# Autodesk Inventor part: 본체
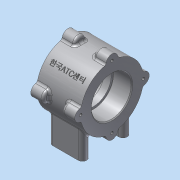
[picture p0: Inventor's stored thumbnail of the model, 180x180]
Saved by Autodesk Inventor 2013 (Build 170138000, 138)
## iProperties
Created: 2015-03
Part Number: 본체
Material: 알루미늄 6061
Document SubType Name: Modeling
Designer: 교육생
Density: 2.71 g/cm^3
Mass: 450.776 g
Surface Area: 332.744 cm^2
Volume: 166.338 cm^3
Author: 교육생
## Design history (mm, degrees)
sketch "스케치1"
  geometry: L1 (19, -31.749)-(19, -56); L2 (19, -56)-(29, -56); L3 (29, -56)-(29, -22.978); L4 (-29, -22.978)-(-29, -56); L5 (-29, -56)-(-19, -56); L6 (-19, -56)-(-19, -31.749); A1 r 37 centre (0, 0) between (19, -31.749) and (29, -22.978); 3 further points
  constraints: 12 end point, 4 parallel, 4 point on circle, 3 horizontal alignment, 2 midpoint, 2 perpendicular, 1 centre point, 1 coincident, 1 vertical
  dimensions: "d0" = 74 diameter of A1; "d4" = 10 distance of L1.end L2.end; "d5" = 56 distance from line of L2 point (0, 0); "d6" = 48 distance of point (24, -56) point (-24, -56)
extrude "돌출1" new body sketch "스케치1" stored distance "d2" = 52; taper "d3" = 0 deg
extrude "돌출2" join sketch "스케치1" stored distance "d7" = 40; taper "d8" = 0 deg
sketch "스케치2"
  geometry: A1 r 37 centre (0, 0) between (0, 37) and (-6.969, 36.338) reference; A2 r 7 centre (0, 37) between (6.969, 36.338) and (-6.969, 36.338)
  constraints: 5 point on circle, 1 centre point, 1 vertical alignment
  dimensions: "d9" = 7 radius of A2
extrude "돌출3" join sketch "스케치2" distance "d11" = 15; taper "d12" = 0 deg
hole "구멍1" diameter "d15" = 3.242; stored, may be unused: countersink angle "d19" = 90 deg, drill point angle "d21" = 118 deg; dims "d13" = 10, "d14" = 10, "d16" = 8, "d17" = 4, "d18" = 2, "d20" = 11
fillet "모깎기1" dims "d25" = 5
fillet "모깎기2" dims "d26" = 3
fillet "모깎기3" dims "d27" = 3
fillet "모깎기4" dims "d28" = 3
fillet "모깎기5" dims "d29" = 3
fillet "모깎기6" dims "d30" = 3
hole "구멍3" diameter "d42" = 4.134; stored, may be unused: countersink angle "d46" = 90 deg, drill point angle "d48" = 118 deg; dims "d40" = 10, "d41" = 10, "d43" = 6, "d44" = 4, "d45" = 2, "d47" = 8
hole "구멍4" diameter "d51" = 4.134; stored, may be unused: countersink angle "d55" = 90 deg, drill point angle "d57" = 118 deg; dims "d49" = 10, "d50" = 10, "d52" = 6, "d53" = 4, "d54" = 2, "d56" = 8
hole "구멍5" diameter "d60" = 4.134; stored, may be unused: countersink angle "d64" = 90 deg, drill point angle "d66" = 118 deg; dims "d58" = 10, "d59" = 10, "d61" = 6, "d62" = 4, "d63" = 2, "d65" = 8
hole "구멍6" diameter "d69" = 4.134; stored, may be unused: countersink angle "d73" = 90 deg, drill point angle "d75" = 118 deg; dims "d67" = 10, "d68" = 10, "d70" = 6, "d71" = 4, "d72" = 2, "d74" = 8
hole "구멍7" diameter "d78" = 42; stored, may be unused: countersink angle "d82" = 90 deg, drill point angle "d84" = 118 deg; dims "d76" = 10, "d77" = 10, "d79" = 6, "d80" = 47, "d81" = 22, "d83" = 8
hole "구멍8" diameter "d87" = 47; stored, may be unused: countersink angle "d91" = 90 deg, drill point angle "d93" = 0 deg; dims "d85" = 10, "d86" = 10, "d88" = 6, "d89" = 47, "d90" = 22, "d92" = 22
fillet "모깎기7" dims "d94" = 0.3
chamfer "모따기1" distance "d95" = 1; stored, may be unused: second distance "d96" = 2, angle "d97" = 45 deg
node "작업 평면2"
  node "작업 평면1"
sketch "스케치4"
  geometry: L1 (-26, 18.921)-(-26, -18.921) reference; 3 further points
  constraints: 1 horizontal alignment, 1 midpoint, 1 other
  dimensions: "d101" = 26 distance from line of point (0, 0) L1
feature "엠보싱1" sketch "스케치4" dims "d102" = 0.5, "d103" = 0
node "솔리드1"
pattern_circular "원형 패턴1" dims angle "d23" = 360 deg
mirror "대칭1"
other parameters: "d98" = 45 deg, "d99" = 37
